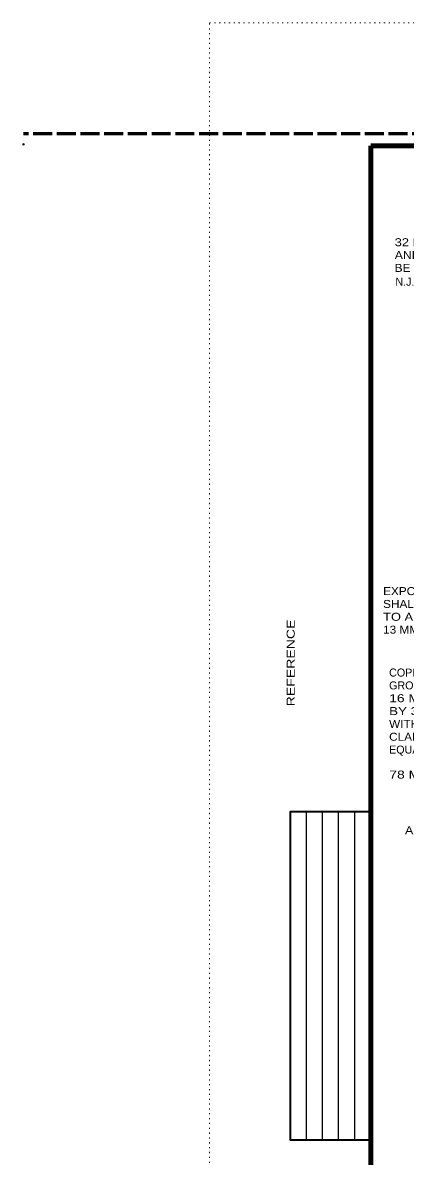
# Model space of a CAD drawing. Extents: x 312583 to 312854, y 144419 to 144597.
# Drawn here: x 312583.5 to 312619.8, y 144489.1 to 144596.8 of the extents above; entities that cross this region are included whole.
import ezdxf

# ---------------------------------------------------------------- set-up
doc = ezdxf.new("R2010")
doc.units = 0
doc.header["$LTSCALE"] = 0.3
doc.header["$PDMODE"] = 32
doc.header["$PDSIZE"] = 0.15
doc.linetypes.add('DOTTED', pattern=[1.5, 0.3, -1.2])
doc.linetypes.add('LONG_DASHED', pattern=[7.5, 6, -1.5])
doc.layers.add('1', color=7, linetype='Continuous', lineweight=13)
doc.layers.add('63', color=7, linetype='DOTTED', lineweight=13)

msp = doc.modelspace()

# ---------------------------------------------------------------- linework, layer by layer
at = {"layer": '1', "linetype": 'LONG_DASHED', "lineweight": 60}
msp.add_line((312851.75, 144586.2246), (312583.526, 144586.2246), dxfattribs=at)
at = {"layer": '1', "lineweight": 158}
for p, q in [((312616.5, 144585.0846), (312849, 144585.0846)), ((312616.5, 144581.3229), (312616.5, 144585.0846)), ((312616.5, 144423.1446), (312616.5, 144582.2946))]:
    msp.add_line(p, q, dxfattribs=at)
at = {"layer": '1'}
msp.add_line((312618.9165, 144542.57), (312618.9228, 144542.57), dxfattribs=at)
at = {"layer": '1', "lineweight": 25}
for p, q in [((312610.4087, 144490.6573), (312610.4087, 144521.8756)), ((312611.9315, 144490.6573), (312611.9315, 144521.8756)), ((312613.4543, 144490.6573), (312613.4543, 144521.8756)), ((312614.9772, 144490.6573), (312614.9772, 144521.8756))]:
    msp.add_line(p, q, dxfattribs=at)
at = {"layer": '1', "lineweight": 35}
msp.add_lwpolyline([(312616.5, 144490.6573), (312608.8858, 144490.6573), (312608.8858, 144521.8756), (312616.5, 144521.8756)], dxfattribs=at)
at = {"layer": '1'}
msp.add_point((312583.526, 144585.2246), dxfattribs=at)
at = {"layer": '63'}
for p, q in [((312601.2, 144596.7846), (312853.5, 144596.7846)), ((312601.2, 144418.5846), (312601.2, 144596.7846))]:
    msp.add_line(p, q, dxfattribs=at)

# ---------------------------------------------------------------- texts
at = {"layer": '1'}
for s, width, p in [('32 BY 32 MM GALV. ANGLE FRAME', 1.2, (312618.7787, 144575.5533)), ('AND CAST IRONCOVER. DETAILS WILL', 1.15, (312618.7787, 144574.3333)), ('BE FURNISHED UPON', 1.1, (312618.7787, 144573.1133)), ('EXPOSED EDGES ', 1.1, (312617.6789, 144542.4164)), ('SHALL BE ROUNDED ', 1.1, (312617.6789, 144541.1964)), ('TO A RADIUS OF', 1.2, (312617.6789, 144539.9764)), ('13 MM.', 1.1, (312617.6789, 144538.7564)), ('16 MM DIA. ', 1.3, (312618.2477, 144532.2415)), ('BY 3.7 M LONG', 1.25, (312618.2477, 144531.0215)), ('WITH CAST BRONZE', 1.1, (312618.2477, 144529.8015)), ('CLAMP  OR APPROVED', 1.1, (312618.2477, 144528.5815)), ('78 MM DIA.  P.V.C.  CONDUIT', 1.3, (312618.2623, 144524.9896)), ('ASSEMBLIES.  SEE DETAIL', 1.15, (312619.757, 144519.7051))]:
    msp.add_text(s, height=0.76, dxfattribs=dict(at, width=width)).set_placement(p)
for s, p in [('N.J.D.O.T.', (312618.8427, 144571.7967)), ('COPPER WELD', (312618.2477, 144534.6815)), ('GROUND ROD', (312618.2477, 144533.4615)), ('EQUAL.', (312618.2477, 144527.3615))]:
    msp.add_text(s, height=0.76, dxfattribs=at).set_placement(p)
at = {"layer": '1', "width": 1.3}
msp.add_text('REFERENCE                                                              ', height=0.7682, rotation=90, dxfattribs=at).set_placement((312609.2854, 144531.8549))

doc.saveas('drawing.dxf')
